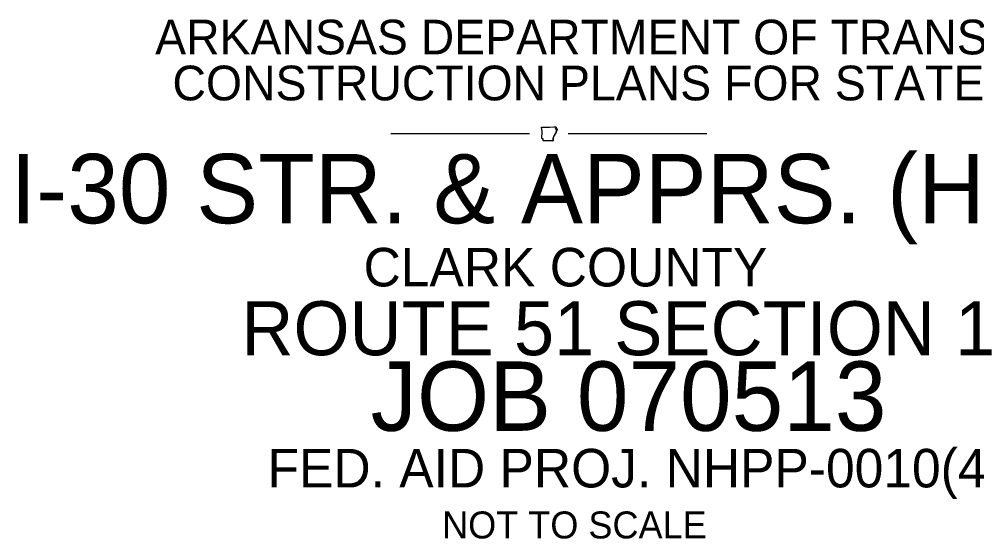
# Model space of a CAD drawing. Extents: x 8749 to 11879, y 13275 to 15339.
# Drawn here: x 9585 to 10827, y 14628 to 15302 of the extents above; entities that cross this region are included whole.
import ezdxf

# ---------------------------------------------------------------- set-up
doc = ezdxf.new("R2010")
doc.units = 0
doc.layers.add('R_Draft', color=7, linetype='Continuous')

msp = doc.modelspace()

# ---------------------------------------------------------------- linework, layer by layer
at = {"layer": 'R_Draft'}
for p, q in [((10067.194360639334, 15154.039271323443), (10247.19436066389, 15154.039271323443)), ((10297.194360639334, 15154.039271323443), (10477.19436066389, 15154.039271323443))]:
    msp.add_line(p, q, dxfattribs=at)
for points in [[(10262.878192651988, 15162.356227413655), (10268.33556765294, 15162.352852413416), (10273.124692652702, 15162.362977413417), (10278.77444265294, 15162.450727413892), (10281.393442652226, 15162.511477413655)], [(10263.273067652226, 15147.590602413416), (10263.576817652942, 15156.746977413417), (10262.878192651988, 15162.356227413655)], [(10280.583442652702, 15159.875602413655), (10283.14506765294, 15160.007227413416)], [(10277.515567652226, 15144.296602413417), (10265.146192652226, 15144.316852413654), (10265.13944265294, 15147.047227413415)]]:
    msp.add_lwpolyline(points, dxfattribs=at)
for points in [[(10281.822067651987, 15156.757102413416), (10281.83556765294, 15156.659227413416), (10281.77819265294, 15156.554602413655), (10281.757942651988, 15156.449977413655), (10281.768067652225, 15156.345352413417), (10281.660067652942, 15156.287977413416), (10281.56556765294, 15156.220477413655), (10281.619567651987, 15156.139477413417), (10281.72081765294, 15156.065227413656), (10281.822067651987, 15156.007852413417), (10281.88619265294, 15155.950477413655), (10281.90306765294, 15155.812102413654), (10281.919942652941, 15155.724352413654), (10281.953692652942, 15155.602852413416), (10281.967192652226, 15155.518477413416), (10281.906442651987, 15155.417227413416), (10281.83556765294, 15155.396977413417), (10281.761317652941, 15155.420602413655), (10281.67356765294, 15155.427352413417), (10281.602692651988, 15155.359852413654), (10281.552067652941, 15155.265352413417), (10281.501442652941, 15155.170852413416), (10281.46431765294, 15155.089852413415), (10281.427192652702, 15155.002102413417), (10281.352942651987, 15154.900852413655), (10281.261817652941, 15154.883977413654), (10281.153817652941, 15154.856977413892), (10281.089692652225, 15154.782727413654), (10281.099817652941, 15154.657852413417), (10281.160567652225, 15154.573477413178), (10281.207817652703, 15154.468852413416), (10281.241567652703, 15154.377727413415), (10281.224692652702, 15154.262977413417), (10281.177442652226, 15154.178602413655), (10281.116692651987, 15154.127977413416), (10281.089692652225, 15154.019977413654), (10281.045817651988, 15153.938977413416), (10281.005317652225, 15153.911977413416), (10280.924317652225, 15153.918727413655), (10280.836567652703, 15153.935602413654), (10280.762317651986, 15153.928852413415), (10280.691442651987, 15153.891727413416), (10280.620567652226, 15153.915352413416), (10280.546317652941, 15153.996352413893), (10280.485567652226, 15154.057102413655), (10280.418067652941, 15154.080727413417), (10280.347192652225, 15154.043602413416), (10280.333692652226, 15153.932227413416), (10280.367442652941, 15153.817477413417), (10280.397817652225, 15153.662227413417), (10280.367442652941, 15153.567727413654), (10280.35731765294, 15153.412477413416)], [(10281.393442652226, 15162.511477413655), (10281.410317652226, 15162.362977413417), (10281.457567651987, 15162.285352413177), (10281.46431765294, 15162.143602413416), (10281.521692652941, 15162.082852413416), (10281.619567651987, 15162.022102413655), (10281.707317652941, 15161.924227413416), (10281.72756765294, 15161.809477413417), (10281.700567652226, 15161.691352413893), (10281.69381765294, 15161.559727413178), (10281.680317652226, 15161.444977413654), (10281.660067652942, 15161.340352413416), (10281.579067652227, 15161.255977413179), (10281.501442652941, 15161.195227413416), (10281.43056765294, 15161.124352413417), (10281.37994265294, 15161.050102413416), (10281.292192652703, 15160.969102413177), (10281.204442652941, 15160.884727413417), (10281.133567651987, 15160.810477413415), (10281.06269265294, 15160.715977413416), (10281.028942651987, 15160.611352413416), (10280.951317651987, 15160.537102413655), (10280.890567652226, 15160.469602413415), (10280.809567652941, 15160.378477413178), (10280.769067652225, 15160.287352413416), (10280.691442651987, 15160.182727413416), (10280.674567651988, 15160.081477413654), (10280.623942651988, 15160.000477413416), (10280.620567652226, 15159.986977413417)], [(10283.107942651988, 15160.003852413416), (10283.14506765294, 15160.007227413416), (10283.259817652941, 15159.885727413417), (10283.31044265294, 15159.784477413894), (10283.384692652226, 15159.727102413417), (10283.469067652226, 15159.696727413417), (10283.533192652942, 15159.619102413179), (10283.577067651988, 15159.534727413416), (10283.553442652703, 15159.460477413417), (10283.45894265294, 15159.453727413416), (10283.35431765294, 15159.436852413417), (10283.253067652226, 15159.440227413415), (10283.17206765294, 15159.372727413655), (10283.246317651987, 15159.281602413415), (10283.344192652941, 15159.197227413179), (10283.371192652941, 15159.106102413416), (10283.317192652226, 15159.018352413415), (10283.209192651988, 15158.971102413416), (10283.104567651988, 15158.930602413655), (10283.010067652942, 15158.849602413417), (10282.966192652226, 15158.771977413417), (10282.861567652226, 15158.738227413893), (10282.75356765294, 15158.707852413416), (10282.659067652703, 15158.697727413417), (10282.551067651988, 15158.677477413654), (10282.446442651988, 15158.626852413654), (10282.402567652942, 15158.539102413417), (10282.416067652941, 15158.414227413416), (10282.412692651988, 15158.282602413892), (10282.524067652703, 15158.238727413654), (10282.621942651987, 15158.235352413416), (10282.716442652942, 15158.184727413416), (10282.706317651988, 15158.110477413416), (10282.635442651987, 15158.015977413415), (10282.551067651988, 15157.941727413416), (10282.466692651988, 15157.904602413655), (10282.389067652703, 15157.833727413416), (10282.416067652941, 15157.762852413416), (10282.48694265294, 15157.715602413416), (10282.53756765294, 15157.637977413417), (10282.530817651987, 15157.567102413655), (10282.449817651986, 15157.516477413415), (10282.362067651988, 15157.536727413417), (10282.297942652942, 15157.621102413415), (10282.223692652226, 15157.648102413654), (10282.159567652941, 15157.678477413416), (10282.085317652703, 15157.634602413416), (10282.085317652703, 15157.536727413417), (10282.058317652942, 15157.432102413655), (10282.081942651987, 15157.354477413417), (10282.112317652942, 15157.246477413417), (10282.108942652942, 15157.165477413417), (10282.081942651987, 15157.050727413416), (10282.024567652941, 15156.932602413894), (10281.95706765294, 15156.895477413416), (10281.93006765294, 15157.023727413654), (10281.916567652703, 15157.128352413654), (10281.876067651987, 15157.189102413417), (10281.822067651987, 15157.192477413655), (10281.751192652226, 15157.141852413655), (10281.67356765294, 15157.064227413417), (10281.575692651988, 15156.979852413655), (10281.51831765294, 15156.895477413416), (10281.548692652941, 15156.790852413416), (10281.62294265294, 15156.763852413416), (10281.680317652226, 15156.784102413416), (10281.710692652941, 15156.851602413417), (10281.768067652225, 15156.861727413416), (10281.822067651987, 15156.757102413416)], [(10265.13944265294, 15147.047227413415), (10265.152942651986, 15147.040477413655), (10265.08881765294, 15147.084352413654), (10265.001067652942, 15147.128227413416), (10264.903192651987, 15147.134977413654), (10264.778317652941, 15147.151852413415), (10264.673692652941, 15147.161977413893), (10264.565692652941, 15147.232852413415), (10264.450942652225, 15147.158602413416), (10264.32269265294, 15147.104602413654), (10264.248442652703, 15147.165352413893), (10264.150567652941, 15147.124852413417), (10264.08306765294, 15147.145102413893), (10263.964942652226, 15147.064102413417), (10263.853567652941, 15147.094477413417), (10263.772567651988, 15147.070852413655), (10263.671317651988, 15147.074227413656), (10263.651067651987, 15147.188977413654), (10263.55319265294, 15147.205852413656), (10263.468817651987, 15147.253102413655), (10263.411442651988, 15147.371227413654), (10263.370942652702, 15147.462352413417), (10263.273067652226, 15147.590602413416)], [(10278.031942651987, 15148.947352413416), (10277.998192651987, 15148.869727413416), (10277.961067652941, 15148.734727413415), (10277.971192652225, 15148.619977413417), (10278.021817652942, 15148.522102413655), (10278.102817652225, 15148.468102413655), (10278.190567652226, 15148.390477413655), (10278.183817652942, 15148.272352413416), (10278.13319265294, 15148.228477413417), (10278.015067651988, 15148.258852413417), (10277.92394265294, 15148.299352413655), (10277.846317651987, 15148.275727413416), (10277.741692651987, 15148.225102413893), (10277.664067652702, 15148.214977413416), (10277.667442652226, 15148.052977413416), (10277.772067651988, 15147.938227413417), (10277.863192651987, 15147.938227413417), (10277.967817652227, 15147.924727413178), (10278.00494265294, 15147.803227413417), (10277.944192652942, 15147.701977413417), (10277.842942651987, 15147.651352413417), (10277.714692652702, 15147.712102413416), (10277.623567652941, 15147.776227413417), (10277.532442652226, 15147.836977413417), (10277.417692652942, 15147.867352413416), (10277.353567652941, 15147.853852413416), (10277.323192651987, 15147.712102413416), (10277.377192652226, 15147.583852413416), (10277.464942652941, 15147.496102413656), (10277.545942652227, 15147.381352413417), (10277.532442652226, 15147.296977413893), (10277.471692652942, 15147.273352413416), (10277.363692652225, 15147.249727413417), (10277.29956765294, 15147.215977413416), (10277.282692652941, 15147.188977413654), (10277.31644265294, 15147.074227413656), (10277.346817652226, 15146.949352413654), (10277.346817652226, 15146.854852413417), (10277.309692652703, 15146.767102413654), (10277.252317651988, 15146.632102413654), (10277.259067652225, 15146.544352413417), (10277.29956765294, 15146.503852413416), (10277.35019265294, 15146.517352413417), (10277.417692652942, 15146.564602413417), (10277.461567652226, 15146.618602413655), (10277.498692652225, 15146.686102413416), (10277.569567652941, 15146.743477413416), (10277.657317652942, 15146.692852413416), (10277.677567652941, 15146.588227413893), (10277.626942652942, 15146.497102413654), (10277.55606765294, 15146.456602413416), (10277.468317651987, 15146.422852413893), (10277.40419265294, 15146.348602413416), (10277.42106765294, 15146.260852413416), (10277.471692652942, 15146.213602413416), (10277.596567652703, 15146.237227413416), (10277.680942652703, 15146.274352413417), (10277.728192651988, 15146.321602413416), (10277.785567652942, 15146.378977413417), (10277.815942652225, 15146.436352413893), (10277.859817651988, 15146.497102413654), (10277.937442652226, 15146.513977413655), (10277.97456765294, 15146.463352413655), (10277.961067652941, 15146.348602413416), (10277.913817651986, 15146.240602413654), (10277.849692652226, 15146.149477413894), (10277.778817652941, 15146.085352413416), (10277.69106765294, 15145.946977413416), (10277.707942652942, 15145.818727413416), (10277.741692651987, 15145.714102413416), (10277.788942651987, 15145.633102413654), (10277.86994265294, 15145.649977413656), (10277.961067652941, 15145.660102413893), (10278.015067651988, 15145.616227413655), (10278.00831765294, 15145.521727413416), (10277.940817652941, 15145.430602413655), (10277.876692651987, 15145.342852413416), (10277.842942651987, 15145.221352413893), (10277.856442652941, 15145.136977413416), (10277.856442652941, 15145.059352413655), (10277.829442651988, 15144.974977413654), (10277.782192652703, 15144.927727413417), (10277.657317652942, 15144.931102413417), (10277.525692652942, 15144.944602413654), (10277.45481765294, 15144.904102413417), (10277.468317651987, 15144.789352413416), (10277.545942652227, 15144.704977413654), (10277.599942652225, 15144.661102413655), (10277.677567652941, 15144.566602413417), (10277.711317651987, 15144.488977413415), (10277.701192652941, 15144.421477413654), (10277.653942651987, 15144.364102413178), (10277.515567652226, 15144.296602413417)], [(10280.35731765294, 15153.412477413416), (10280.279692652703, 15153.314602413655), (10280.16494265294, 15153.375352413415), (10280.16494265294, 15153.456352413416), (10280.181817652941, 15153.540727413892), (10280.14131765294, 15153.594727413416), (10280.070442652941, 15153.571102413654), (10280.070442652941, 15153.466477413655), (10280.06369265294, 15153.365227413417), (10280.043442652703, 15153.220102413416), (10280.090692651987, 15153.176227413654), (10280.19869265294, 15153.162727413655), (10280.276317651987, 15153.142477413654), (10280.32356765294, 15153.064852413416), (10280.320192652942, 15152.970352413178), (10280.283067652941, 15152.879227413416), (10280.229067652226, 15152.804977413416), (10280.144692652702, 15152.777977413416), (10280.077192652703, 15152.821852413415), (10280.050192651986, 15152.909602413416), (10280.019817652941, 15152.987227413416), (10279.962442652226, 15153.044602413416), (10279.90169265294, 15152.980477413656), (10279.888192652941, 15152.862352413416), (10279.891567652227, 15152.761102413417), (10279.891567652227, 15152.622727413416), (10279.979317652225, 15152.531602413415), (10280.033317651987, 15152.426977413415), (10280.016442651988, 15152.332477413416), (10279.952317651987, 15152.221102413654), (10279.925317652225, 15152.123227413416), (10279.898317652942, 15151.991602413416), (10279.90169265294, 15151.846477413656), (10279.878067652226, 15151.704727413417), (10279.830817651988, 15151.610227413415), (10279.743067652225, 15151.532602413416), (10279.685692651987, 15151.481977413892), (10279.638442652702, 15151.431352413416), (10279.614817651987, 15151.330102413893), (10279.597942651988, 15151.259227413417), (10279.53381765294, 15151.174852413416), (10279.483192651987, 15151.168102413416), (10279.442692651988, 15151.201852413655), (10279.42919265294, 15151.259227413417), (10279.42919265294, 15151.316602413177), (10279.402192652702, 15151.373977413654), (10279.317817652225, 15151.397602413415), (10279.250317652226, 15151.394227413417), (10279.21994265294, 15151.346977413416), (10279.263817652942, 15151.215352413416), (10279.280692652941, 15151.130977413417), (10279.257067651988, 15151.016227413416), (10279.270567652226, 15151.002727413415), (10279.149067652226, 15150.938602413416), (10279.051192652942, 15150.928477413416), (10278.970192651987, 15150.904852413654), (10278.892567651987, 15150.854227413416), (10278.85544265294, 15150.779977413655), (10278.801442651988, 15150.719227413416), (10278.754192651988, 15150.661852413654), (10278.69006765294, 15150.634852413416), (10278.619192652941, 15150.648352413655), (10278.524692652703, 15150.658477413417), (10278.470692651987, 15150.590977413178), (10278.487567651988, 15150.493102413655), (10278.551692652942, 15150.435727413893), (10278.646192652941, 15150.408727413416), (10278.744067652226, 15150.415477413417), (10278.838567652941, 15150.425602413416), (10278.92631765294, 15150.378352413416), (10278.909442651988, 15150.287227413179), (10278.82506765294, 15150.243352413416), (10278.700192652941, 15150.229852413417), (10278.598942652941, 15150.239977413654), (10278.47744265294, 15150.212977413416), (10278.416692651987, 15150.135352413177), (10278.450442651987, 15150.017227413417), (10278.58206765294, 15149.969977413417), (10278.642817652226, 15149.858602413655), (10278.646192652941, 15149.753977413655), (10278.602317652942, 15149.615602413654), (10278.541567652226, 15149.551477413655), (10278.423442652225, 15149.524477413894), (10278.332317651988, 15149.507602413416), (10278.318817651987, 15149.352352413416), (10278.278317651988, 15149.274727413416), (10278.207442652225, 15149.251102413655), (10278.106192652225, 15149.301727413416), (10278.045442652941, 15149.325352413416), (10277.971192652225, 15149.359102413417), (10277.876692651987, 15149.416477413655), (10277.805817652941, 15149.406352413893), (10277.826067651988, 15149.257852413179), (10277.832817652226, 15149.251102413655), (10277.913817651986, 15149.139727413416), (10277.994817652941, 15149.051977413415), (10278.031942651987, 15148.947352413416)]]:
    msp.add_spline(points, degree=3, dxfattribs=at)

# ---------------------------------------------------------------- texts
for s, height, p in [('ARKANSAS DEPARTMENT OF TRANSPORTATION ', 44.999999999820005, (9761.640563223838, 15256.539271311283)), ('CONSTRUCTION PLANS FOR STATE HIGHWAY', 44.999999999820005, (9784.066744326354, 15196.939271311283)), ('I-30 STR. & APPRS. (HWY. 51) (S)', 90, (9574.11125432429, 15037.530636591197)), ('CLARK COUNTY', 49.99999999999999, (10031.971158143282, 14955.68829054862)), ('ROUTE 51 SECTION 1', 69.99999999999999, (9873.432622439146, 14866.480583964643)), ('JOB 070513', 90, (10041.136517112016, 14768.467873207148)), ('FED. AID PROJ. NHPP-0010(48)', 49.99999999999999, (9907.411714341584, 14695.082454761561)), ('NOT TO SCALE', 34.99999999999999, (10133.8403663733, 14628.94069402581))]:
    msp.add_text(s, height=height, dxfattribs=at).set_placement(p)

doc.saveas('drawing.dxf')
